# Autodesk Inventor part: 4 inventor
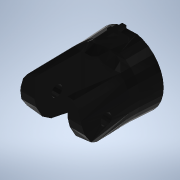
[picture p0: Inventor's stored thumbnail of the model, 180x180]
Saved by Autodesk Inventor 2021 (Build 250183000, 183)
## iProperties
Created: 2022-10
Part Number: 4 inventor
Material: Genérico
Document SubType Name: Modeling
Designer: Yair Obed
Density: 1 g/cm^3
Appearance: Valor por defecto
Author: Yair Obed
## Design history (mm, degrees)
node "4"
  node "MeshFeature1"
